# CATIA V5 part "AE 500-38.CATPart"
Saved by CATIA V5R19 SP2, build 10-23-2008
Part number: BS 500-38
Bounding box of the stored display mesh (mm): x -22.494 to 22.494, y -22.494 to 22.494, z 0 to 126
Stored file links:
  C:\Users\Bora\Desktop\3D Katı model\AE serisi\AE 500\BS 500-38.CATPart
  C:\Program Files\Dassault Systemes\B19\intel_a\reffiles\standard\MetricThickPitch.txt
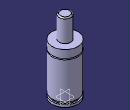
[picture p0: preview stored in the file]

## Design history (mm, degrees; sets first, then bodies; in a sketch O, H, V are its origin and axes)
Body1 (main body)
  Sketch1 on yz-plane, origin (0, 0, 0), H (0, 1, 0), V (0, 0, 1)
    point P1 (22.5, 71.5)
    point P8 (22.5, 73.5)
    point P9 (22.5, 73.5)
    point P10 (22.5, 71.5)
    point P11 (10, 124)
    point P13 (10, 124)
    line L1 (22.5, 71.5) -> (22.5, 8)
    line L2 (22.5, 4) -> (22.5, 0)
    line L3 (20, 8) -> (20, 4)
    line L4 (22.5, 87) -> (22.5, 73.5)
    arc A1 centre (22.5, 72.5) radius 1 from (22.5, 73.5) to (22.5, 71.5) ccw
    line L5 (10, 124) -> (10, 87)
    arc A2 centre (8, 124) radius 2 from (10, 124) to (8, 126) ccw
    line L6 (8, 126) -> (0, 126)
    point P15 (0, 126)
    line L7 (10, 87) -> (22.5, 87)
    line L8 (0, 0) -> (22.5, 0)
    line L9 (20, 8) -> (22.5, 8)
    line L10 (20, 4) -> (22.5, 4)
    tangency: L6 A2
    coincidence: P15 V, P1 P10, P8 P9, P11 P13
    horizontal: L7 H, L8 H, L9 H, L10 H
  Shaft1: profile Sketch1, axis Sketch1.V, angle 360
  Sketch2 on face of Shaft1 from Sketch1.L8, origin (0, 0, 0), H (1, 0, 0), V (0, -1, 0)
    point P1 (10, 0)
    distance P1 V = 10
  Hole1: placed by Sketch2, at (10, 0, 0) direction (0, 0, 1), diameter 6.647, depth 13, threaded "M8", thread diameter 8, thread depth 13, pitch 1.25
  CircPattern1: of Hole1, instances 2, angular step 180, axis from xy-plane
